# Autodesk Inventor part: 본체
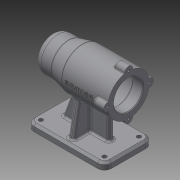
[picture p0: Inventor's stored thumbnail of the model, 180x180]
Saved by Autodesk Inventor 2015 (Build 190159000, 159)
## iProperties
Created: 2019-07
Part Number: 본체
Material: 일반
Document SubType Name: Modeling
Designer: now
Density: 1 g/cm^3
Appearance: 기본값
Mass: 238.662 g
Surface Area: 654.094 cm^2
Volume: 238.662 cm^3
Author: now
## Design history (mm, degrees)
sketch "스케치1"
  geometry: L1 (56, 25)-(31, 25); L2 (31, 25)-(11, 30); L3 (11, 30)-(-56, 30); L4 (-56, 30)-(-56, 0); L5 (-56, 0)-(56, 0); L6 (56, 0)-(56, 25); 2 further points
  constraints: 12 end point, 2 parallel, 2 perpendicular, 1 coincident, 1 horizontal, 1 midpoint
  dimensions: "d0" = 25 distance of L1.start L1.end; "d1" = 45 horizontal distance of L2.end L1.start; "d2" = 112 distance of L4.end L5.end; "d3" = 30 distance of L3.end L4.end; "d4" = 25 distance of L5.end L1.start
revolve "회전1" sketch "스케치1" stored, may be unused: angle "d5" = 90 deg
node "작업 평면1"
sketch "스케치2"
  geometry: L1 (-56, 35)-(56, 35); L2 (56, 35)-(56, -35); L3 (56, -35)-(-56, -35); L4 (-56, -35)-(-56, 35); L5 (-56, 35)-(56, -35); L6 (56, 35)-(-56, -35); 1 further point
  constraints: 12 end point, 2 midpoint, 2 parallel, 1 horizontal, 1 perpendicular
  dimensions: "d7" = 112 distance of L2.end L3.end; "d8" = 70 distance of L1.end L2.end
extrude "돌출1" join sketch "스케치2" distance "d9" = 10; taper "d10" = 0 deg
sketch "스케치3"
  geometry: L1 (56, 35)-(-56, 35) reference; L2 (-56, 35)-(-56, -35) reference; L3 (-56, -35)-(56, -35) reference; L4 (56, -35)-(56, 35) reference; L5 (-36, -4)-(31, -4); L6 (31, -4)-(31, 4); L7 (31, 4)-(-36, 4); L8 (-36, 4)-(-36, -4); L9 (-4, -28)-(4, -28); L10 (4, -28)-(4, 28); L11 (4, 28)-(-4, 28); L12 (-4, 28)-(-4, -28); 1 further point
  constraints: 16 end point, 4 parallel, 2 horizontal, 2 perpendicular
  dimensions: "d11" = 8 distance of L10.end L11.end; "d12" = 8 distance of L7.end L5.start; "d13" = 4 distance from line of L5 point (0, 0); "d14" = 4 distance from line of point (0, 0) L10; "d15" = 20 distance between parallel lines of L2 L8; "d16" = 25 distance between parallel lines of L4 L6; "d17" = 7 distance between parallel lines of L3 L9; "d18" = 7 distance between parallel lines of L1 L11
extrude "돌출2" new body sketch "스케치3" stored distance "d19" = 10; taper "d20" = 0 deg
feature "면 기울기1" dims angle "d21" = 10 deg
feature "면 기울기2" dims angle "d22" = 20 deg
feature "결합1"
  node "솔리드1"
sketch "스케치4"
  geometry: C1 r 30 at (0, 0) reference
hole "구멍1" sketch "스케치4" at (0, 0) diameter "d23" = 42; stored, may be unused: countersink angle "d27" = 90 deg, drill point angle "d29" = 0 deg; dims "d24" = 6, "d25" = 4, "d26" = 2, "d28" = 15
sketch "스케치5"
  geometry: C1 r 21 at (0, 0) reference
hole "구멍2" sketch "스케치5" at (0, 0) diameter "d30" = 48; stored, may be unused: countersink angle "d34" = 90 deg, drill point angle "d36" = 0 deg; dims "d31" = 6, "d32" = 4, "d33" = 2, "d35" = 54
sketch "스케치6"
  geometry: C1 r 24 at (0, 0) reference
hole "구멍3" sketch "스케치6" at (0, 0) diameter "d37" = 42; stored, may be unused: countersink angle "d41" = 90 deg, drill point angle "d43" = 0 deg; dims "d38" = 6, "d39" = 4, "d40" = 2, "d42" = 12
sketch "스케치7"
  geometry: C1 r 21 at (0, 0) reference
hole "구멍4" sketch "스케치7" at (0, 0) diameter "d44" = 35; stored, may be unused: countersink angle "d48" = 90 deg, drill point angle "d50" = 0 deg; dims "d45" = 6, "d46" = 4, "d47" = 2, "d49" = 18
sketch "스케치8"
  geometry: C1 r 17.5 at (0, 0) reference
hole "구멍5" sketch "스케치8" at (0, 0) diameter "d51" = 32; stored, may be unused: countersink angle "d55" = 90 deg, drill point angle "d57" = 0 deg; dims "d52" = 6, "d53" = 4, "d54" = 2, "d56" = 4
sketch "스케치9"
  geometry: C1 r 16 at (0, 0) reference
hole "구멍6" sketch "스케치9" at (0, 0) diameter "d58" = 21; stored, may be unused: countersink angle "d62" = 90 deg, drill point angle "d64" = 0 deg; dims "d59" = 6, "d60" = 4, "d61" = 2, "d63" = 3
fillet "모깎기1" dims "d65" = 3
fillet "모깎기2" dims "d66" = 3
fillet "모깎기3" dims "d67" = 0.3
sketch "스케치10"
  geometry: C1 r 6 at (-30, 0); 1 further point
  constraints: 1 centre point, 1 horizontal alignment, 1 other
  dimensions: "d68" = 12 diameter of C1
extrude "돌출3" join sketch "스케치10" distance "d69" = 16; taper "d70" = 0 deg
fillet "모깎기4" dims "d71" = 3
fillet "모깎기5" dims "d72" = 1
sketch "스케치11"
  geometry: A1 r 6 centre (60, 0) between (60.171, -5.998) and (60.171, 5.998) reference; A2 r 6 centre (30, 30) between (35.998, 30.171) and (24.002, 30.171) reference; A3 r 6 centre (0, 0) between (-0.171, 5.998) and (-0.171, -5.998) reference; A4 r 6 centre (30, -30) between (24.002, -30.171) and (35.998, -30.171) reference
hole "구멍7" sketch "스케치11" at (0, 0), (30, -30), (60, 0), (30, 30) diameter "d76" = 3.242; stored, may be unused: countersink angle "d80" = 90 deg, drill point angle "d82" = 118 deg; dims "d77" = 8, "d78" = 4, "d79" = 2, "d81" = 11
sketch "스케치12"
  geometry: C1 r 3 at (10, -60); C2 r 3 at (10, -10); 1 further point
  constraints: 2 centre point
  dimensions: "d83" = 50 distance of C2.centre C1.centre; "d85" = 6 diameter of C1; "d86" = 6 diameter of C2; "d87" = 25 vertical distance of point (56, -35) C1.centre; "d88" = 46 horizontal distance of point (56, -35) C1.centre; "d89" = 46 horizontal distance of C2.centre point (56, -35)
extrude "돌출4" cut sketch "스케치12" stored distance "d90" = 16; taper "d91" = 0 deg
fillet "모깎기6" dims "d92" = 10
chamfer "모따기1" distance "d93" = 3; stored, may be unused: second distance "d94" = 2, angle "d95" = 45 deg
fillet "모깎기7" dims "d96" = 10
fillet "모깎기8" dims "d97" = 3
fillet "모깎기9" dims "d98" = 3
fillet "모깎기10" dims "d99" = 3
fillet "모깎기11" dims "d100" = 3
chamfer "모따기2" distance "d101" = 1; stored, may be unused: second distance "d102" = 2, angle "d103" = 45 deg
node "작업 평면2"
sketch "스케치13"
  geometry: L1 (56, 36)-(56, 30.171) reference; 2 further points
  constraints: 1 horizontal alignment, 1 other
  dimensions: "d105" = 42 distance from line of point (14, 0) L1
feature "엠보싱1" sketch "스케치13" dims "d0" = 25, "d1" = 45, "d2" = 112, "d3" = 30, "d4" = 25, "d106" = 0.5, "d107" = 0
pattern_circular "원형 패턴1" dims "d74" = 360 deg
mirror "대칭1"
node "솔리드2"
other parameters: "d104" = -30.5
